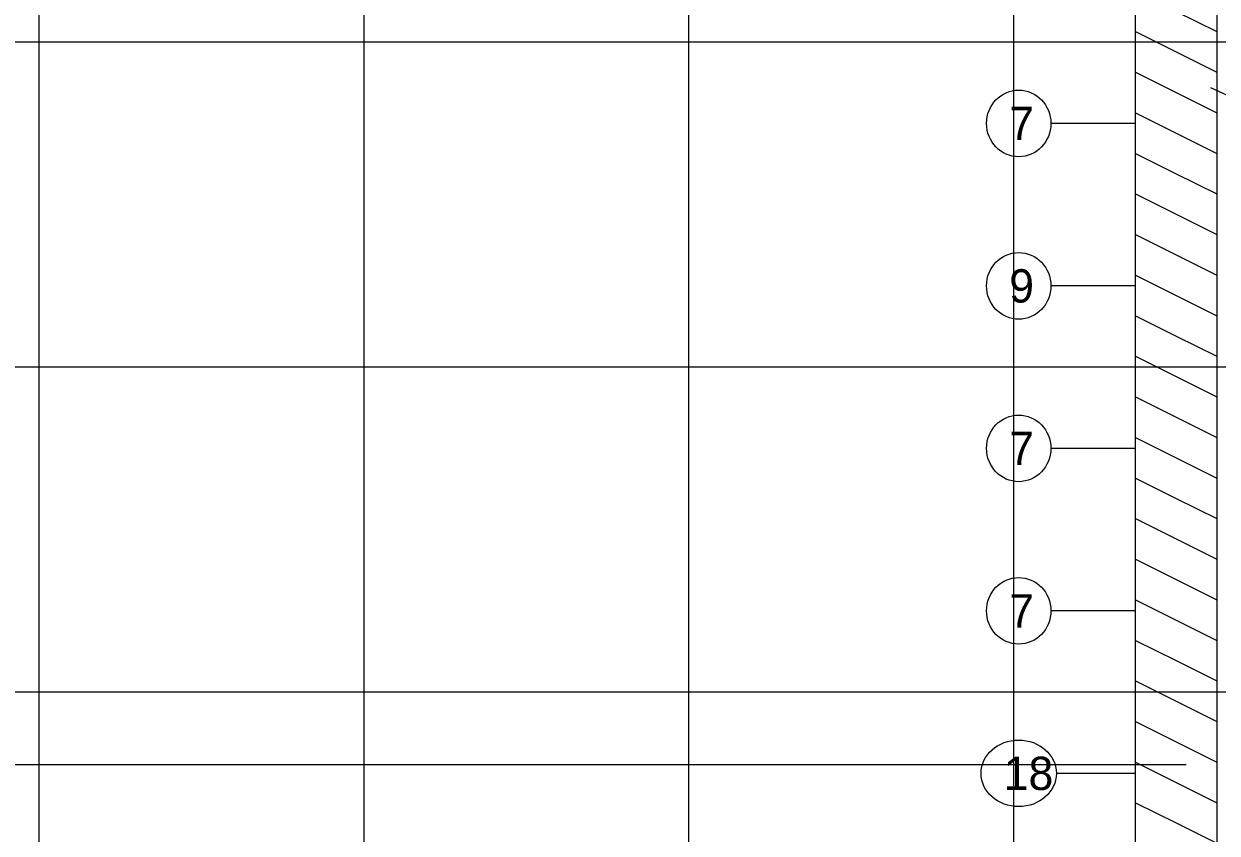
# Model space of a CAD drawing. Extents: x 278618 to 280654, y 171155 to 171855.
# Drawn here: x 280043.65 to 280080.38, y 171223.4 to 171248.3 of the extents above; entities that cross this region are included whole.
import ezdxf

# ---------------------------------------------------------------- set-up
doc = ezdxf.new("R2010")
doc.units = 0
for name, color, linetype in [('Prop Road Sect_ Boring - Material (Outline)', 7, 'Continuous'), ('Prop Road Sect_ Boring - Peripheral (SPT Oval + Leader)', 7, 'Continuous'), ('Prop Road Sect_ Boring - Peripheral (SPT Tx)', 7, 'Continuous'), ('Prop Road Sect_ Material - Contact (General - Major)', 7, 'Continuous'), ('Prop Strc Sect_ Grid - minor', 7, 'Continuous'), ('Prop Strc Sect_ Material - Contact (General - Major)', 7, 'Continuous')]:
    doc.layers.add(name, color=color, linetype=linetype)

msp = doc.modelspace()

# ---------------------------------------------------------------- linework, layer by layer
at = {"layer": 'Prop Road Sect_ Boring - Material (Outline)'}
for p, q in [((280079.123, 171248.69), (280080.372, 171248.066)), ((280079.123, 171248.69), (280080.372, 171248.066)), ((280077.875, 171248.066), (280080.372, 171246.817)), ((280077.875, 171248.066), (280080.372, 171246.817)), ((280077.875, 171248.066), (280080.372, 171246.817)), ((280077.875, 171248.066), (280080.372, 171246.817)), ((280080.372, 171248.066), (280080.375, 171248.065)), ((280080.372, 171248.066), (280080.375, 171248.065)), ((280080.372, 171248.066), (280080.375, 171248.065)), ((280080.372, 171248.066), (280080.375, 171248.065)), ((280077.875, 171246.817), (280079.123, 171246.193)), ((280077.875, 171246.817), (280079.123, 171246.193)), ((280080.372, 171246.817), (280080.375, 171246.816)), ((280080.372, 171246.817), (280080.375, 171246.816)), ((280079.123, 171246.193), (280080.372, 171245.569)), ((280079.123, 171246.193), (280080.372, 171245.569)), ((280077.875, 171245.569), (280080.372, 171244.32)), ((280077.875, 171245.569), (280080.372, 171244.32)), ((280077.875, 171245.569), (280080.372, 171244.32)), ((280077.875, 171245.569), (280080.372, 171244.32)), ((280080.372, 171245.569), (280080.375, 171245.567)), ((280080.372, 171245.569), (280080.375, 171245.567)), ((280080.372, 171245.569), (280080.375, 171245.567)), ((280080.372, 171245.569), (280080.375, 171245.567)), ((280077.875, 171244.32), (280079.123, 171243.695)), ((280077.875, 171244.32), (280079.123, 171243.695)), ((280080.372, 171244.32), (280080.375, 171244.319)), ((280080.372, 171244.32), (280080.375, 171244.319)), ((280079.123, 171243.695), (280080.372, 171243.071)), ((280079.123, 171243.695), (280080.372, 171243.071)), ((280077.875, 171243.071), (280080.372, 171241.822)), ((280077.875, 171243.071), (280080.372, 171241.822)), ((280077.875, 171243.071), (280080.372, 171241.822)), ((280077.875, 171243.071), (280080.372, 171241.822)), ((280080.372, 171243.071), (280080.375, 171243.07)), ((280080.372, 171243.071), (280080.375, 171243.07)), ((280080.372, 171243.071), (280080.375, 171243.07)), ((280080.372, 171243.071), (280080.375, 171243.07)), ((280077.875, 171241.822), (280079.123, 171241.198)), ((280077.875, 171241.822), (280079.123, 171241.198)), ((280080.372, 171241.822), (280080.375, 171241.821)), ((280080.372, 171241.822), (280080.375, 171241.821)), ((280079.123, 171241.198), (280080.372, 171240.574)), ((280079.123, 171241.198), (280080.372, 171240.574)), ((280077.875, 171240.574), (280080.372, 171239.325)), ((280077.875, 171240.574), (280080.372, 171239.325)), ((280077.875, 171240.574), (280080.372, 171239.325)), ((280077.875, 171240.574), (280080.372, 171239.325)), ((280080.372, 171240.574), (280080.375, 171240.572)), ((280080.372, 171240.574), (280080.375, 171240.572)), ((280080.372, 171240.574), (280080.375, 171240.572)), ((280080.372, 171240.574), (280080.375, 171240.572)), ((280077.875, 171239.325), (280079.123, 171238.7)), ((280077.875, 171239.325), (280079.123, 171238.7)), ((280080.372, 171239.325), (280080.375, 171239.324)), ((280080.372, 171239.325), (280080.375, 171239.324)), ((280079.123, 171238.7), (280080.372, 171238.076)), ((280079.123, 171238.7), (280080.372, 171238.076)), ((280077.875, 171238.076), (280080.372, 171236.827)), ((280077.875, 171238.076), (280080.372, 171236.827)), ((280077.875, 171238.076), (280080.372, 171236.827)), ((280077.875, 171238.076), (280080.372, 171236.827)), ((280080.372, 171238.076), (280080.375, 171238.075)), ((280080.372, 171238.076), (280080.375, 171238.075)), ((280080.372, 171238.076), (280080.375, 171238.075)), ((280080.372, 171238.076), (280080.375, 171238.075)), ((280077.875, 171236.827), (280079.123, 171236.203)), ((280077.875, 171236.827), (280079.123, 171236.203)), ((280080.372, 171236.827), (280080.375, 171236.826)), ((280080.372, 171236.827), (280080.375, 171236.826)), ((280079.123, 171236.203), (280080.372, 171235.579)), ((280079.123, 171236.203), (280080.372, 171235.579)), ((280077.875, 171235.579), (280080.372, 171234.33)), ((280077.875, 171235.579), (280080.372, 171234.33)), ((280077.875, 171235.579), (280080.372, 171234.33)), ((280077.875, 171235.579), (280080.372, 171234.33)), ((280080.372, 171235.579), (280080.375, 171235.577)), ((280080.372, 171235.579), (280080.375, 171235.577)), ((280080.372, 171235.579), (280080.375, 171235.577)), ((280080.372, 171235.579), (280080.375, 171235.577)), ((280077.875, 171234.33), (280079.123, 171233.705)), ((280077.875, 171234.33), (280079.123, 171233.705)), ((280080.372, 171234.33), (280080.375, 171234.329)), ((280080.372, 171234.33), (280080.375, 171234.329)), ((280079.123, 171233.705), (280080.372, 171233.081)), ((280079.123, 171233.705), (280080.372, 171233.081)), ((280077.875, 171233.081), (280080.372, 171231.832)), ((280077.875, 171233.081), (280080.372, 171231.832)), ((280077.875, 171233.081), (280080.372, 171231.832)), ((280077.875, 171233.081), (280080.372, 171231.832)), ((280080.372, 171233.081), (280080.375, 171233.08)), ((280080.372, 171233.081), (280080.375, 171233.08)), ((280080.372, 171233.081), (280080.375, 171233.08)), ((280080.372, 171233.081), (280080.375, 171233.08)), ((280077.875, 171231.832), (280079.123, 171231.208)), ((280077.875, 171231.832), (280079.123, 171231.208)), ((280080.372, 171231.832), (280080.375, 171231.831)), ((280080.372, 171231.832), (280080.375, 171231.831)), ((280079.123, 171231.208), (280080.372, 171230.584)), ((280079.123, 171231.208), (280080.372, 171230.584)), ((280077.875, 171230.584), (280080.372, 171229.335)), ((280077.875, 171230.584), (280080.372, 171229.335)), ((280077.875, 171230.584), (280080.372, 171229.335)), ((280077.875, 171230.584), (280080.372, 171229.335)), ((280080.372, 171230.584), (280080.375, 171230.582)), ((280080.372, 171230.584), (280080.375, 171230.582)), ((280080.372, 171230.584), (280080.375, 171230.582)), ((280080.372, 171230.584), (280080.375, 171230.582)), ((280077.875, 171229.335), (280079.123, 171228.71)), ((280077.875, 171229.335), (280079.123, 171228.71)), ((280080.372, 171229.335), (280080.375, 171229.334)), ((280080.372, 171229.335), (280080.375, 171229.334)), ((280079.123, 171228.71), (280080.372, 171228.086)), ((280079.123, 171228.71), (280080.372, 171228.086)), ((280077.875, 171228.086), (280080.372, 171226.837)), ((280077.875, 171228.086), (280080.372, 171226.837)), ((280077.875, 171228.086), (280080.372, 171226.837)), ((280077.875, 171228.086), (280080.372, 171226.837)), ((280080.372, 171228.086), (280080.375, 171228.085)), ((280080.372, 171228.086), (280080.375, 171228.085)), ((280080.372, 171228.086), (280080.375, 171228.085)), ((280080.372, 171228.086), (280080.375, 171228.085)), ((280077.875, 171226.837), (280079.123, 171226.213)), ((280077.875, 171226.837), (280079.123, 171226.213)), ((280080.372, 171226.837), (280080.375, 171226.836)), ((280080.372, 171226.837), (280080.375, 171226.836)), ((280079.123, 171226.213), (280080.372, 171225.589)), ((280079.123, 171226.213), (280080.372, 171225.589)), ((280077.875, 171225.589), (280080.372, 171224.34)), ((280077.875, 171225.589), (280080.372, 171224.34)), ((280077.875, 171225.589), (280080.372, 171224.34)), ((280077.875, 171225.589), (280080.372, 171224.34)), ((280080.372, 171225.589), (280080.375, 171225.587)), ((280080.372, 171225.589), (280080.375, 171225.587)), ((280080.372, 171225.589), (280080.375, 171225.587)), ((280080.372, 171225.589), (280080.375, 171225.587)), ((280077.875, 171224.34), (280079.123, 171223.715)), ((280077.875, 171224.34), (280079.123, 171223.715)), ((280080.372, 171224.34), (280080.375, 171224.339)), ((280080.372, 171224.34), (280080.375, 171224.339)), ((280079.123, 171223.715), (280080.372, 171223.091)), ((280079.123, 171223.715), (280080.372, 171223.091))]:
    msp.add_line(p, q, dxfattribs=at)
msp.add_lwpolyline([(280077.875, 171251.243), (280080.375, 171251.243), (280080.375, 171196.243), (280077.875, 171196.243)], close=True, dxfattribs=at)
at = {"layer": 'Prop Road Sect_ Boring - Peripheral (SPT Oval + Leader)'}
for p, q in [((280077.875, 171245.243), (280075.265, 171245.243)), ((280077.875, 171240.243), (280075.265, 171240.243)), ((280077.875, 171235.243), (280075.265, 171235.243)), ((280077.875, 171230.243), (280075.265, 171230.243)), ((280077.875, 171225.243), (280075.435, 171225.243))]:
    msp.add_line(p, q, dxfattribs=at)
for centre, major_axis, ratio in [((280074.275, 171245.243), (0, 1.025), 0.966391), ((280074.275, 171240.243), (0, 1.025), 0.966391), ((280074.275, 171235.243), (0, 1.025), 0.966391), ((280074.275, 171230.243), (0, 1.025), 0.966391), ((280074.275, 171225.243), (1.16, 0), 0.883591)]:
    msp.add_ellipse(centre, major_axis=major_axis, ratio=ratio, dxfattribs=at)
at = {"layer": 'Prop Road Sect_ Material - Contact (General - Major)'}
msp.add_line((280079.435, 171225.505), (280034.309, 171225.505), dxfattribs=at)
at = {"layer": 'Prop Strc Sect_ Grid - minor'}
for p, q in [((280044.125, 171188.859), (280044.125, 171293.859)), ((280054.125, 171188.859), (280054.125, 171293.859)), ((280064.125, 171188.859), (280064.125, 171293.859)), ((280074.125, 171188.859), (280074.125, 171293.859)), ((280174.125, 171247.743), (280024.125, 171247.743)), ((280174.125, 171237.743), (280024.125, 171237.743)), ((280174.125, 171227.743), (280024.125, 171227.743))]:
    msp.add_line(p, q, dxfattribs=at)
at = {"layer": 'Prop Strc Sect_ Material - Contact (General - Major)'}
msp.add_line((280080.178, 171246.344), (280108.478, 171233.344), dxfattribs=at)

# ---------------------------------------------------------------- texts
at = {"layer": 'Prop Road Sect_ Boring - Peripheral (SPT Tx)'}
for s, p in [('7', (280073.984, 171244.73)), ('9', (280073.984, 171239.73)), ('7', (280073.984, 171234.73)), ('7', (280073.984, 171229.73)), ('18', (280073.815, 171224.73))]:
    msp.add_text(s, height=1.025, dxfattribs=at).set_placement(p)

doc.saveas('drawing.dxf')
